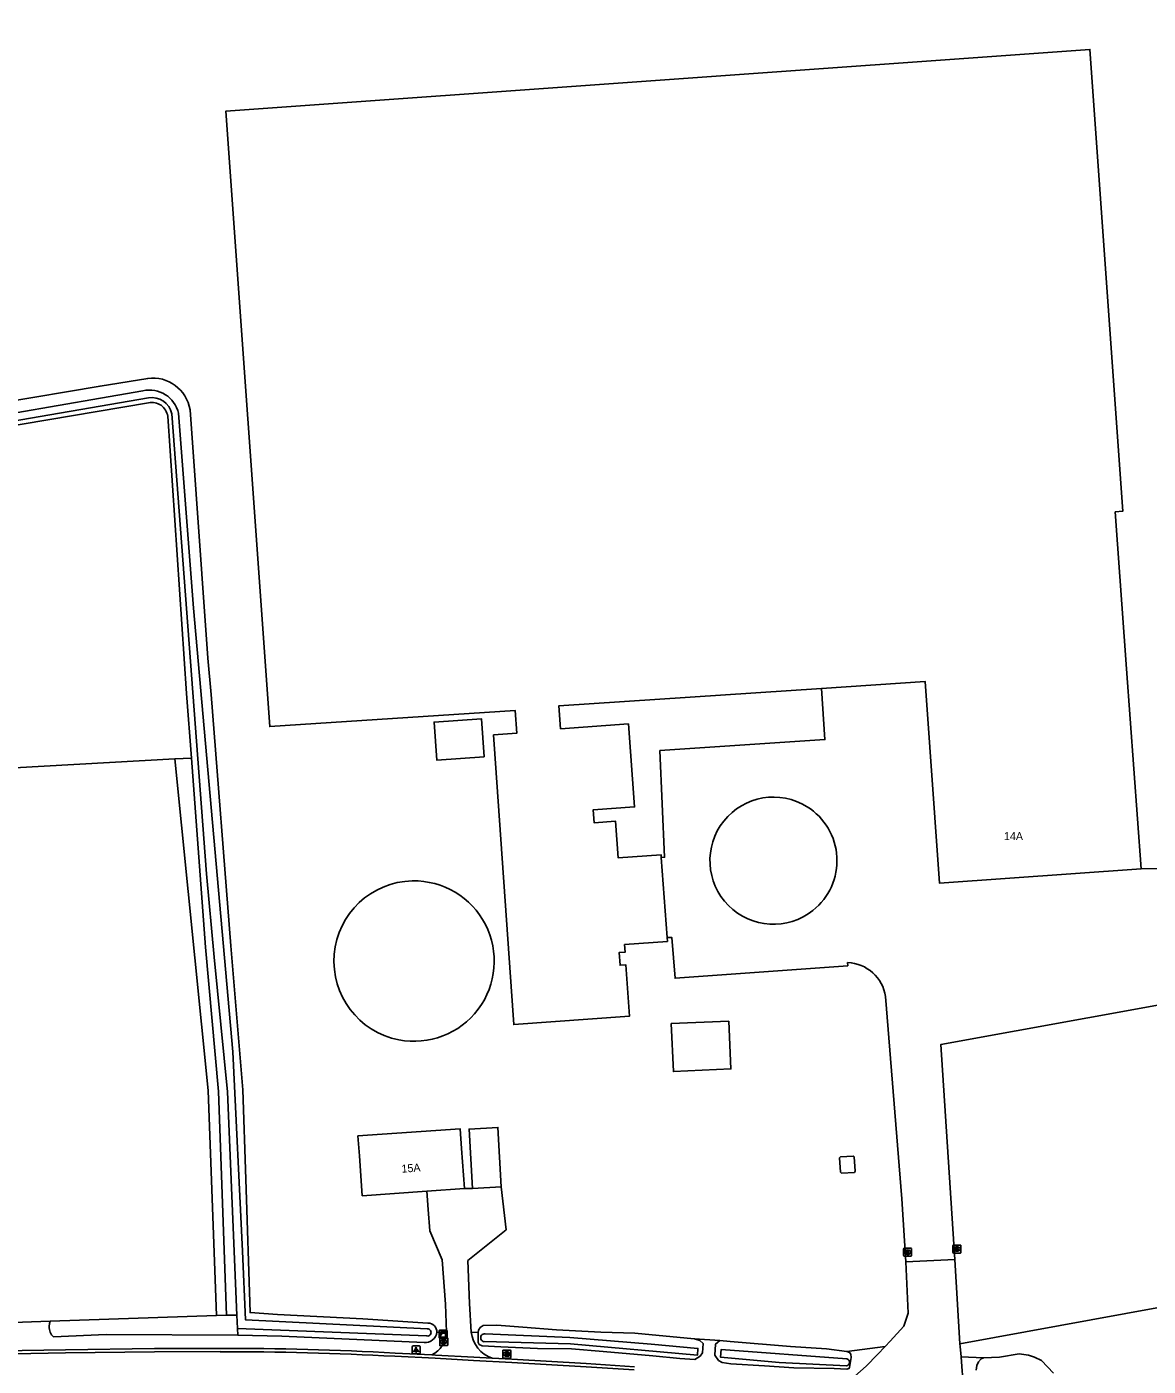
# Model space of a CAD drawing. Extents: x 162515 to 163909, y 388494 to 389773.
# Drawn here: x 162765.8 to 162906, y 389047 to 389214.3 of the extents above; entities that cross this region are included whole.
import ezdxf

# ---------------------------------------------------------------- set-up
doc = ezdxf.new("R2010")
doc.units = 0
for name, color, linetype in [('IMGEO_Bouwland', 7, 'Continuous'), ('IMGEO_Brandkraan', 7, 'Continuous'), ('IMGEO_Erf', 7, 'Continuous'), ('IMGEO_Grasland_overig', 7, 'Continuous'), ('IMGEO_Groenvoorziening', 7, 'Continuous'), ('IMGEO_Kast', 7, 'Continuous'), ('IMGEO_Kolk', 7, 'Continuous'), ('IMGEO_Lichtpunt', 7, 'Continuous'), ('IMGEO_Loofbos', 7, 'Continuous'), ('IMGEO_Opslagtank', 7, 'Continuous'), ('IMGEO_Pand', 7, 'Continuous'), ('IMGEO_Pand_nummerreeks', 7, 'Continuous'), ('IMGEO_Rijbaan_lokaal_gesloten', 7, 'Continuous'), ('IMGEO_Rijbaan_lokaal_halfverhard', 7, 'Continuous'), ('IMGEO_Rijbaan_lokaal_open', 7, 'Continuous'), ('IMGEO_Rioolput', 7, 'Continuous'), ('IMGEO_Waterloop', 7, 'Continuous')]:
    doc.layers.add(name, color=color, linetype=linetype)

msp = doc.modelspace()

# ---------------------------------------------------------------- linework, layer by layer
at = {"layer": 'IMGEO_Bouwland'}
msp.add_lwpolyline([(162768.72, 389052.58), (162762.9, 389052.38)], dxfattribs=at)
at = {"layer": 'IMGEO_Brandkraan'}
for p, q in [((162825.28, 389048.05), (162825.28, 389048.91)), ((162825.35, 389048.98), (162826.2, 389048.98)), ((162825.76, 389048.76), (162825.79, 389048.76)), ((162826.28, 389048.91), (162826.28, 389048.05)), ((162826.2, 389047.98), (162825.35, 389047.98)), ((162825.79, 389048.2), (162825.76, 389048.2))]:
    msp.add_line(p, q, dxfattribs=at)
for points in [[(162825.28, 389048.05), (162825.28, 389048.91)], [(162825.35, 389048.98), (162826.2, 389048.98)], [(162825.62, 389048.68), (162825.62, 389048.28), (162825.84, 389048.28)], [(162825.86, 389048.68), (162825.62, 389048.68)], [(162825.8, 389048.6), (162825.75, 389048.6), (162825.75, 389048.52)], [(162825.75, 389048.52), (162825.8, 389048.52)], [(162825.81, 389048.45), (162825.75, 389048.45), (162825.75, 389048.37)], [(162825.75, 389048.37), (162825.81, 389048.37)], [(162826.28, 389048.91), (162826.28, 389048.05)], [(162826.2, 389047.98), (162825.35, 389047.98)]]:
    msp.add_lwpolyline(points, dxfattribs=at)
for centre, radius, start, end in [((162825.35, 389048.9), 0.0765, 91.552, 178.448), ((162825.35, 389048.9), 0.0765, 91.552, 178.448), ((162825.8, 389048.56), 0.0379, 267.8285, 90.9355), ((162825.81, 389048.41), 0.0404, 269.8759, 90.5077), ((162825.84, 389048.53), 0.251, 268.6676, 293.5347), ((162825.86, 389048.53), 0.145, 59.4692, 91.5367), ((162825.88, 389048.58), 0.0922, 285.5137, 58.1501), ((162825.89, 389048.39), 0.105, 301.3115, 78.989), ((162826.2, 389048.9), 0.0765, 1.552, 88.448), ((162826.2, 389048.9), 0.0765, 1.552, 88.448), ((162825.35, 389048.06), 0.0765, 181.552, 268.448), ((162825.35, 389048.06), 0.0765, 181.552, 268.448), ((162826.2, 389048.06), 0.0765, 271.552, 358.448), ((162826.2, 389048.06), 0.0765, 271.552, 358.448)]:
    msp.add_arc(centre, radius, start, end, dxfattribs=at)
for centre, major_axis, ratio, start_param, end_param in [((162825.76, 389048.48), (-0.387, 0.002), 0.722429, 4.712389, 7.853982), ((162825.79, 389048.48), (-0.39, 0.002), 0.717154, 1.570796, 4.712389)]:
    msp.add_ellipse(centre, major_axis=major_axis, ratio=ratio, start_param=start_param, end_param=end_param, dxfattribs=at)
at = {"layer": 'IMGEO_Erf'}
for points in [[(162715.83, 389259.29), (162718.51, 389257.59), (162720.35, 389255.01), (162721.13, 389251.92), (162723.99, 389234.84), (162725.28, 389227.42), (162727.94, 389211.76), (162729.42, 389203.63), (162735.57, 389170), (162736.15, 389167.25), (162737.83, 389164.93), (162740.34, 389163.54), (162762.58, 389167.33), (162774.94, 389169.41), (162780.89, 389170.37)], [(162786.19, 389166.44), (162788.39, 389135.41), (162788.82, 389130.87), (162791.29, 389099.48), (162792.78, 389081.48), (162793.15, 389070.35), (162793.68, 389053.66), (162797.11, 389053.44), (162807.8, 389052.87), (162815.91, 389052.36)], [(162882.42, 389049.74), (163026.73, 389076.11), (163024.56, 389085.79), (163040.38, 389088.23), (163032.81, 389139.1), (163036.74, 389139.46)], [(162822.21, 389051.18), (162822.22, 389051.47), (162822.43, 389051.79), (162822.83, 389052.03), (162824.52, 389052.08), (162827.78, 389051.83), (162831.99, 389051.51), (162837.52, 389051.22), (162841.79, 389051.1), (162848.31, 389050.46), (162849.25, 389050.37)], [(162852.39, 389050.16), (162853.7, 389050.05), (162861.22, 389049.41), (162865.74, 389049.15), (162868.3, 389048.82)], [(162885.37, 389047.99), (162887.37, 389048.09), (162889.8, 389048.49), (162890.97, 389048.36), (162891.74, 389048.1), (162892.6, 389047.68), (162894.1, 389046.11)]]:
    msp.add_lwpolyline(points, dxfattribs=at)
for centre, radius, start, end in [((162781.51, 389165.67), 4.74, 9.4366, 97.5946), ((162815.9, 389051.22), 1.14, 358.5192, 89.4374)]:
    msp.add_arc(centre, radius, start, end, dxfattribs=at)
at = {"layer": 'IMGEO_Grasland_overig'}
for points in [[(162789.49, 389053.3), (162788.46, 389081.4), (162784.28, 389122.83)], [(162790.74, 389053.34), (162789.73, 389081.3), (162788.12, 389099.3), (162786.36, 389122.91)], [(162885.37, 389047.99), (162882.55, 389048.13)], [(162884.45, 389046.48), (162884.52, 389047.05), (162884.72, 389047.52), (162885.08, 389047.88), (162885.37, 389047.99)]]:
    msp.add_lwpolyline(points, dxfattribs=at)
at = {"layer": 'IMGEO_Groenvoorziening'}
for points in [[(162815.44, 389049.94), (162797.64, 389050.73), (162792.17, 389050.85)], [(162817.04, 389051.19), (162818.23, 389051.2)], [(162821.33, 389051.23), (162822.21, 389051.18)], [(162849.25, 389050.37), (162849.9, 389050.16), (162850.34, 389049.79), (162850.25, 389048.64), (162849.93, 389048.21), (162849.26, 389047.79), (162847.42, 389047.91), (162844.04, 389048.28), (162837.82, 389048.79), (162833.88, 389049.13), (162829.63, 389049.18), (162825.03, 389049.37), (162822.69, 389049.52), (162822.34, 389049.69), (162822.18, 389049.91), (162822.21, 389051.18)], [(162849.25, 389050.37), (162852.39, 389050.16)], [(162868.3, 389048.82), (162868.62, 389048.69), (162868.76, 389048.46), (162868.82, 389048.05), (162868.63, 389046.8), (162868.54, 389046.66), (162868.27, 389046.58), (162866.71, 389046.67), (162861.65, 389046.77), (162858, 389046.99), (162853.78, 389047.27), (162852.7, 389047.42), (162852.25, 389047.68), (162851.77, 389048.36), (162851.88, 389049.72), (162852.39, 389050.16)], [(162868.3, 389048.82), (162873.08, 389049.44)]]:
    msp.add_lwpolyline(points, dxfattribs=at)
msp.add_arc((162815.61, 389051.37), 1.44, 263.3055, 353.0977, dxfattribs=at)
at = {"layer": 'IMGEO_Kast'}
for p, q in [((162817.31, 389050.54), (162817.31, 389051.38)), ((162817.31, 389051.38), (162817.31, 389050.54)), ((162817.38, 389051.47), (162818.22, 389051.47)), ((162818.22, 389051.47), (162817.38, 389051.47)), ((162818.23, 389050.47), (162817.39, 389050.47)), ((162817.39, 389050.47), (162818.23, 389050.47)), ((162818.31, 389051.39), (162818.31, 389050.55)), ((162818.31, 389050.55), (162818.31, 389051.39))]:
    msp.add_line(p, q, dxfattribs=at)
for points in [[(162817.5, 389051.26), (162818.1, 389051.26), (162818.1, 389051.17), (162817.5, 389051.17), (162817.5, 389051.26)], [(162817.5, 389051.08), (162818.1, 389051.08), (162818.1, 389050.59), (162817.5, 389050.59), (162817.5, 389051.08)]]:
    msp.add_lwpolyline(points, dxfattribs=at)
msp.add_circle((162817.59, 389050.93), 0.0377, dxfattribs=at)
for centre, start, end in [((162817.39, 389051.39), 92.4484, 184.2845), ((162817.39, 389051.39), 92.4484, 184.2845), ((162817.39, 389050.55), 182.4484, 274.2845), ((162817.39, 389050.55), 182.4484, 274.2845), ((162818.23, 389051.39), 2.4484, 94.2845), ((162818.23, 389051.39), 2.4484, 94.2845), ((162818.23, 389050.55), 272.4484, 4.2845), ((162818.23, 389050.55), 272.4484, 4.2845)]:
    msp.add_arc(centre, 0.0779, start, end, dxfattribs=at)
at = {"layer": 'IMGEO_Kolk'}
for p, q in [((162875.44, 389061.71), (162876.3, 389061.71)), ((162881.54, 389061.17), (162881.54, 389062.02)), ((162881.61, 389062.1), (162882.47, 389062.1)), ((162882.03, 389061.88), (162882.05, 389061.88)), ((162882.54, 389062.02), (162882.54, 389061.17)), ((162875.37, 389060.78), (162875.37, 389061.64)), ((162876.3, 389060.71), (162875.44, 389060.71)), ((162875.88, 389060.93), (162875.85, 389060.93)), ((162875.86, 389061.49), (162875.88, 389061.49)), ((162876.37, 389061.64), (162876.37, 389060.78)), ((162882.47, 389061.1), (162881.61, 389061.1)), ((162882.05, 389061.32), (162882.02, 389061.32))]:
    msp.add_line(p, q, dxfattribs=at)
for points in [[(162875.44, 389061.71), (162876.3, 389061.71)], [(162881.54, 389061.17), (162881.54, 389062.02)], [(162881.61, 389062.1), (162882.47, 389062.1)], [(162881.86, 389061.8), (162881.98, 389061.8), (162881.98, 389061.64), (162882.11, 389061.8), (162882.28, 389061.8), (162882.13, 389061.65), (162882.28, 389061.4), (162882.13, 389061.4), (162882.05, 389061.56), (162881.98, 389061.49), (162881.98, 389061.4), (162881.86, 389061.4), (162881.86, 389061.8)], [(162882.54, 389062.02), (162882.54, 389061.17)], [(162875.37, 389060.78), (162875.37, 389061.64)], [(162876.3, 389060.71), (162875.44, 389060.71)], [(162875.69, 389061.41), (162875.81, 389061.41), (162875.81, 389061.26), (162875.94, 389061.41), (162876.11, 389061.41), (162875.96, 389061.26), (162876.11, 389061.01), (162875.96, 389061.01), (162875.88, 389061.17), (162875.81, 389061.11), (162875.81, 389061.01), (162875.69, 389061.01), (162875.69, 389061.41)], [(162876.37, 389061.64), (162876.37, 389060.78)], [(162882.47, 389061.1), (162881.61, 389061.1)]]:
    msp.add_lwpolyline(points, dxfattribs=at)
for centre, start, end in [((162875.45, 389061.63), 91.552, 178.448), ((162875.45, 389061.63), 91.552, 178.448), ((162876.29, 389061.63), 1.552, 88.448), ((162876.29, 389061.63), 1.552, 88.448), ((162881.62, 389062.02), 91.552, 178.448), ((162881.62, 389062.02), 91.552, 178.448), ((162882.46, 389062.02), 1.552, 88.448), ((162882.46, 389062.02), 1.552, 88.448), ((162875.45, 389060.79), 181.552, 268.448), ((162875.45, 389060.79), 181.552, 268.448), ((162876.29, 389060.79), 271.552, 358.448), ((162876.29, 389060.79), 271.552, 358.448), ((162881.62, 389061.17), 181.552, 268.448), ((162881.62, 389061.17), 181.552, 268.448), ((162882.46, 389061.17), 271.552, 358.448), ((162882.46, 389061.17), 271.552, 358.448)]:
    msp.add_arc(centre, 0.0765, start, end, dxfattribs=at)
for centre, major_axis, ratio, start_param, end_param in [((162882.03, 389061.6), (-0.387, 0.002), 0.722429, 4.712389, 7.853982), ((162882.05, 389061.6), (-0.39, 0.002), 0.717154, 1.570796, 4.712389), ((162875.86, 389061.21), (-0.387, 0.002), 0.722429, 4.712389, 7.853982), ((162875.88, 389061.21), (-0.39, 0.002), 0.717154, 1.570796, 4.712389)]:
    msp.add_ellipse(centre, major_axis=major_axis, ratio=ratio, start_param=start_param, end_param=end_param, dxfattribs=at)
at = {"layer": 'IMGEO_Lichtpunt'}
for p, q in [((162813.94, 389049.4), (162813.94, 389048.6)), ((162813.94, 389049.4), (162813.94, 389048.6)), ((162814.85, 389049.5), (162814.04, 389049.5)), ((162814.85, 389049.5), (162814.04, 389049.5)), ((162814.04, 389048.5), (162814.85, 389048.5)), ((162814.04, 389048.5), (162814.85, 389048.5)), ((162814.94, 389048.6), (162814.94, 389049.4)), ((162814.94, 389048.6), (162814.94, 389049.4))]:
    msp.add_line(p, q, dxfattribs=at)
for points in [[(162814.32, 389049.07), (162814.36, 389049.04), (162814.17, 389048.78), (162814.13, 389048.8), (162814.32, 389049.07)], [(162814.42, 389049.02), (162814.47, 389049.02), (162814.47, 389048.7), (162814.42, 389048.7), (162814.42, 389049.02)], [(162814.53, 389049.04), (162814.57, 389049.07), (162814.76, 389048.8), (162814.72, 389048.78), (162814.53, 389049.04)]]:
    msp.add_lwpolyline(points, dxfattribs=at)
msp.add_circle((162814.44, 389049.2), 0.0994, dxfattribs=at)
for centre, start, end in [((162814.04, 389049.4), 90, 180), ((162814.04, 389049.4), 90, 180), ((162814.04, 389048.6), 180, 270), ((162814.04, 389048.6), 180, 270), ((162814.85, 389049.4), 0, 90), ((162814.85, 389049.4), 0, 90), ((162814.85, 389048.6), 270, 0), ((162814.85, 389048.6), 270, 360)]:
    msp.add_arc(centre, 0.0946, start, end, dxfattribs=at)
at = {"layer": 'IMGEO_Loofbos'}
for points in [[(162780.99, 389167.33), (162739.73, 389160.37), (162737.68, 389161.41)], [(162786.36, 389122.91), (162785.76, 389130.99), (162783.4, 389165.63)], [(162784.28, 389122.83), (162751.57, 389121.01), (162730.99, 389119.53), (162706.48, 389118.08), (162700.77, 389155.92), (162700.09, 389159.14), (162677.34, 389155.34), (162660.11, 389152.43)], [(162786.36, 389122.91), (162784.28, 389122.83)]]:
    msp.add_lwpolyline(points, dxfattribs=at)
msp.add_arc((162781.39, 389165.34), 2.03, 8.2749, 101.3292, dxfattribs=at)
at = {"layer": 'IMGEO_Opslagtank'}
for start, end in [(91.2929, 258.9949), (259.0012, 91.2866)]:
    msp.add_arc((162814.19, 389097.57), 10.02, start, end, dxfattribs=at)
at = {"layer": 'IMGEO_Pand'}
for points in [[(162845.82, 389100.5), (162845.85, 389100.03), (162840.49, 389099.64), (162840.56, 389098.68), (162839.82, 389098.63), (162839.93, 389097.05), (162840.66, 389097.1), (162841.11, 389090.69), (162826.65, 389089.65), (162824.12, 389125.82), (162827.03, 389126.03), (162826.83, 389128.86), (162796.15, 389126.87), (162790.64, 389203.73), (162898.66, 389211.45), (162902.77, 389153.76), (162901.82, 389153.69), (162903.23, 389134.09), (162905.07, 389109.1)], [(162905.07, 389109.1), (162879.88, 389107.29), (162878.06, 389132.5), (162865.12, 389131.64)], [(162865.12, 389131.64), (162832.3, 389129.47), (162832.51, 389126.59), (162840.98, 389127.21), (162841.74, 389116.83), (162836.56, 389116.45), (162836.68, 389114.86), (162839.36, 389115.06), (162839.7, 389110.46), (162845.07, 389110.85), (162845.09, 389110.53)], [(162822.94, 389123.09), (162817.02, 389122.68), (162816.69, 389127.42), (162822.61, 389127.84), (162822.94, 389123.09)], [(162845.09, 389110.53), (162845.82, 389100.5)], [(162853.52, 389090.08), (162853.79, 389084.1), (162846.61, 389083.77), (162846.34, 389089.76), (162853.52, 389090.08)], [(162821.5, 389069.16), (162821.07, 389076.58), (162824.66, 389076.79), (162825.09, 389069.38)], [(162815.78, 389068.83), (162807.7, 389068.26), (162807.35, 389073.24), (162807.17, 389075.73), (162819.93, 389076.63), (162820.11, 389074.15), (162820.47, 389069.16)], [(162869.21, 389073.11), (162869.33, 389071.31), (162869.22, 389071.18), (162867.61, 389071.08), (162867.49, 389071.19), (162867.36, 389072.99), (162867.48, 389073.11), (162869.08, 389073.21), (162869.21, 389073.11)], [(162820.47, 389069.16), (162815.78, 389068.83)], [(162825.09, 389069.38), (162821.5, 389069.16)]]:
    msp.add_lwpolyline(points, dxfattribs=at)
at = {"layer": 'IMGEO_Rijbaan_lokaal_gesloten'}
for points in [[(162865.12, 389131.64), (162865.54, 389125.25), (162844.91, 389123.87), (162845.51, 389110.55), (162845.09, 389110.53)], [(162905.07, 389109.1), (162917.44, 389109.24), (162918.81, 389099.65)], [(162868.38, 389097.39), (162868.4, 389097), (162846.81, 389095.43), (162846.39, 389100.52), (162845.82, 389100.5)], [(162875.65, 389060.01), (162875.14, 389067.87), (162873.13, 389093.13)], [(162907.75, 389092.44), (162907.84, 389092.21), (162880.03, 389087.17), (162881.79, 389060.3)], [(162881.79, 389060.3), (162875.65, 389060.01)], [(162789.96, 389048.79), (162781.74, 389048.78), (162770.61, 389048.63), (162759.77, 389048.44), (162752.01, 389048.29)], [(162841.7, 389046.5), (162835.68, 389046.9), (162826.39, 389047.43), (162821.62, 389047.69), (162816.83, 389047.96), (162811.78, 389048.21)]]:
    msp.add_lwpolyline(points, dxfattribs=at)
for centre, radius, start, end in [((162859.11, 389110.12), 7.94, 57.9872, 308.4313), ((162859.11, 389110.12), 7.94, 308.4344, 57.984), ((162868.15, 389092.36), 5.04, 8.8237, 87.3675), ((162790.66, 388663.74), 385.04, 86.8557, 90.1054)]:
    msp.add_arc(centre, radius, start, end, dxfattribs=at)
at = {"layer": 'IMGEO_Rijbaan_lokaal_halfverhard'}
for points in [[(162752, 389048.69), (162759.76, 389048.84), (162770.6, 389049.03), (162781.74, 389049.18), (162789.96, 389049.18)], [(162811.81, 389048.6), (162816.39, 389048.38)], [(162823.96, 389047.96), (162826.41, 389047.83), (162835.71, 389047.3), (162841.73, 389046.9)]]:
    msp.add_lwpolyline(points, dxfattribs=at)
msp.add_arc((162790.68, 388664.52), 384.67, 86.8514, 90.1075, dxfattribs=at)
at = {"layer": 'IMGEO_Rijbaan_lokaal_open'}
for points in [[(162818.23, 389051.2), (162818.11, 389054.72), (162817.71, 389060.26), (162816.17, 389063.87), (162815.95, 389066.55), (162815.78, 389068.83)], [(162820.47, 389069.16), (162821.5, 389069.16)], [(162825.09, 389069.38), (162825.7, 389064.01), (162820.91, 389060.15), (162821.12, 389054.79), (162821.33, 389051.23)], [(162873.08, 389049.44), (162873.69, 389050.09), (162875.39, 389051.97), (162875.94, 389053.58), (162875.65, 389060.01)], [(162881.79, 389060.3), (162882.42, 389049.74)], [(162816.39, 389048.38), (162816.85, 389048.35), (162821.65, 389048.09), (162823.96, 389047.96)], [(162873.08, 389049.44), (162872.13, 389048.41), (162870.71, 389046.98), (162869.3, 389045.74), (162868.58, 389045.07)], [(162882.55, 389048.13), (162882.43, 389049.44), (162882.42, 389049.74)], [(162885.18, 389038.78), (162885.25, 389038.88), (162882.86, 389044.66), (162882.71, 389046.36), (162882.55, 389048.13)]]:
    msp.add_lwpolyline(points, dxfattribs=at)
for centre, radius, start, end in [((162814.99, 389051.31), 3.25, 295.657, 358.1884), ((162825.18, 389051.63), 3.87, 185.9892, 251.5441)]:
    msp.add_arc(centre, radius, start, end, dxfattribs=at)
at = {"layer": 'IMGEO_Rioolput'}
for p, q in [((162817.39, 389049.6), (162817.39, 389050.45)), ((162817.46, 389050.53), (162818.31, 389050.53)), ((162817.87, 389050.31), (162817.9, 389050.31)), ((162818.39, 389050.45), (162818.39, 389049.6)), ((162818.31, 389049.53), (162817.46, 389049.53)), ((162817.9, 389049.75), (162817.87, 389049.75))]:
    msp.add_line(p, q, dxfattribs=at)
for points in [[(162817.39, 389049.6), (162817.39, 389050.45)], [(162817.46, 389050.53), (162818.31, 389050.53)], [(162817.97, 389050.22), (162817.72, 389050.23), (162817.72, 389049.83)], [(162817.72, 389049.83), (162817.85, 389049.83), (162817.85, 389049.99), (162817.86, 389049.99)], [(162817.9, 389050.15), (162817.85, 389050.15), (162817.85, 389050.06)], [(162817.85, 389050.06), (162817.9, 389050.06)], [(162817.9, 389049.96), (162817.98, 389049.83), (162818.11, 389049.83), (162818.05, 389049.95)], [(162818.39, 389050.45), (162818.39, 389049.6)], [(162818.31, 389049.53), (162817.46, 389049.53)]]:
    msp.add_lwpolyline(points, dxfattribs=at)
for centre, radius, start, end in [((162817.46, 389050.45), 0.0765, 91.552, 178.448), ((162817.46, 389050.45), 0.0765, 91.552, 178.448), ((162817.86, 389049.94), 0.0533, 26.0293, 88.6989), ((162817.91, 389050.05), 0.0964, 77.0061, 93.1865), ((162817.88, 389050.25), 0.19, 274.7715, 282.9687), ((162817.92, 389050.11), 0.0378, 276.6634, 79.6772), ((162817.97, 389050.12), 0.109, 350.3612, 89.416), ((162817.97, 389050.11), 0.112, 277.5842, 350.9817), ((162817.96, 389049.9), 0.108, 29.5134, 73.7905), ((162818.31, 389050.45), 0.0765, 1.552, 88.448), ((162818.31, 389050.45), 0.0765, 1.552, 88.448), ((162817.46, 389049.6), 0.0765, 181.552, 268.448), ((162817.46, 389049.6), 0.0765, 181.552, 268.448), ((162818.31, 389049.6), 0.0765, 271.552, 358.448), ((162818.31, 389049.6), 0.0765, 271.552, 358.448)]:
    msp.add_arc(centre, radius, start, end, dxfattribs=at)
for centre, major_axis, ratio, start_param, end_param in [((162817.87, 389050.03), (-0.387, 0.002), 0.722429, 4.712389, 7.853982), ((162817.9, 389050.03), (-0.39, 0.002), 0.717154, 1.570796, 4.712389)]:
    msp.add_ellipse(centre, major_axis=major_axis, ratio=ratio, start_param=start_param, end_param=end_param, dxfattribs=at)
at = {"layer": 'IMGEO_Waterloop'}
for points in [[(162780.29, 389168.82), (162743.2, 389162.38)], [(162741.78, 389161.19), (162780.98, 389167.93)], [(162783.91, 389165.95), (162788.24, 389108.47), (162789.18, 389098.06), (162790.87, 389081.26), (162792.03, 389053.36)], [(162815.84, 389051.65), (162793.1, 389052.77), (162792.76, 389061.34), (162791.54, 389086.24), (162786.61, 389141.64), (162784.75, 389166)], [(162768.72, 389052.58), (162789.49, 389053.3)], [(162789.49, 389053.3), (162790.74, 389053.34)], [(162792.03, 389053.36), (162790.74, 389053.34)], [(162792.1, 389051.68), (162792.03, 389053.36)], [(162768.57, 389051.92), (162768.61, 389052.3), (162768.72, 389052.58)], [(162792.1, 389051.68), (162815.79, 389050.74)], [(162792.17, 389050.85), (162792.1, 389051.68)], [(162792.17, 389050.85), (162775.7, 389050.91), (162769.13, 389050.62)], [(162822.95, 389050.03), (162833.74, 389049.75), (162849.61, 389048.34), (162849.67, 389049.18), (162843.83, 389049.71), (162833.66, 389050.55)], [(162833.66, 389050.55), (162823.09, 389051.02)], [(162868.22, 389047.01), (162859.83, 389047.44), (162852.5, 389048.09), (162852.56, 389049.04), (162868.28, 389047.88)]]:
    msp.add_lwpolyline(points, dxfattribs=at)
for centre, radius, start, end in [((162781.09, 389165.16), 3.75, 12.9782, 102.311), ((162781.43, 389165.44), 2.53, 11.6382, 100.1995), ((162770.25, 389051.87), 1.68, 178.0357, 228.2135), ((162815.85, 389051.19), 0.457, 261.5418, 91.9101), ((162823.01, 389050.52), 0.499, 80.386, 263.1263), ((162868.19, 389047.45), 0.44, 273.6889, 78.2896)]:
    msp.add_arc(centre, radius, start, end, dxfattribs=at)

# ---------------------------------------------------------------- texts
at = {"layer": 'IMGEO_Pand_nummerreeks'}
msp.add_text('14A', height=1, dxfattribs=at).set_placement((162887.92, 389112.68))
msp.add_text('15A', height=1, rotation=4.0394, dxfattribs=at).set_placement((162812.65, 389071.13))

doc.saveas('drawing.dxf')
